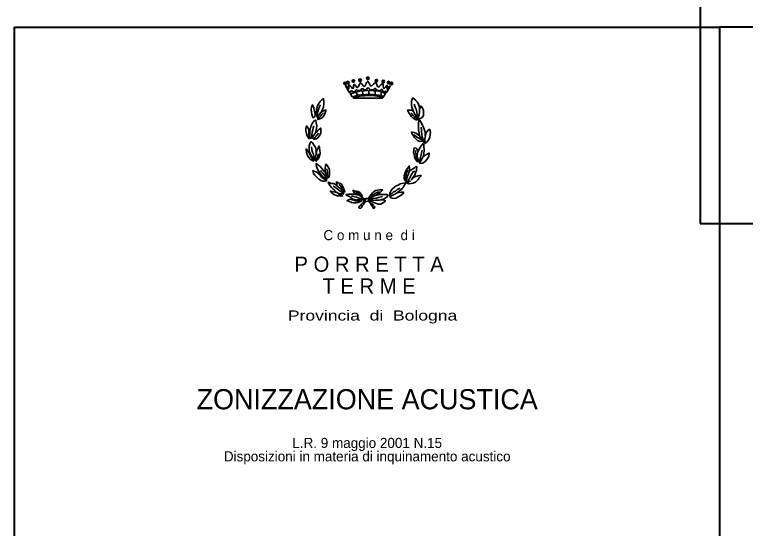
# Model space of a CAD drawing. Extents: x 645880 to 658994, y 884400 to 894744.
# Drawn here: x 645880 to 648057, y 888096 to 889625 of the extents above; entities that cross this region are included whole.
import ezdxf
from ezdxf.enums import TextEntityAlignment as Align

# ---------------------------------------------------------------- set-up
doc = ezdxf.new("R2010")
doc.units = 0
doc.header["$LTSCALE"] = 10
doc.layers.add('62', color=7, linetype='Continuous', lineweight=35)
doc.layers.add('63', color=7, linetype='Continuous', lineweight=35)

msp = doc.modelspace()

# ---------------------------------------------------------------- hatches: boundary and pattern name
at = {"layer": '63'}
for points in [[(646872.77, 889426.73, 1), (646872.77, 889419.06, 1)], [(646889.6, 889431.46, 1), (646889.6, 889423.79, 1)], [(646909.49, 889433.98, 1), (646909.49, 889426.31, 1)], [(646932.74, 889439.66, 1), (646932.74, 889431.99, 1)], [(646958.14, 889432.4, 1), (646958.14, 889424.74, 1)], [(646978.64, 889430.2, 1), (646978.64, 889422.53, 1)], [(646994.86, 889426.73, 1), (646994.86, 889419.06, 1)], [(646864.51, 889424.52, 1), (646864.51, 889416.85, 1)], [(647002.82, 889423.89, 1), (647002.82, 889416.22, 1)]]:
    msp.add_hatch(color=256, dxfattribs=at).paths.add_polyline_path(points)

# ---------------------------------------------------------------- linework, layer by layer
at = {"layer": '62', "lineweight": 40}
msp.add_lwpolyline([(647922.35, 889003.81), (650022.35, 889003.81), (650022.35, 891773.81), (647922.35, 891773.81)], close=True, dxfattribs=at)
at = {"layer": '63'}
for p, q in [((646902.75, 889385.05), (646897.25, 889394.83)), ((646917.44, 889386.94), (646916.22, 889398.29)), ((646935.48, 889388.2), (646935.48, 889398.92)), ((646954.47, 889387.25), (646954.79, 889398.92)), ((646970.99, 889384.1), (646973.75, 889394.2)), ((646758.12, 889261.88), (646757.52, 889255.27)), ((646806.45, 889154.17), (646810.44, 889144.39)), ((646841.61, 889114.78), (646844.37, 889112.57)), ((646853.85, 889104.04), (646855.55, 889101.67)), ((646916.21, 889085.47), (646911.62, 889084.51))]:
    msp.add_line(p, q, dxfattribs=at)
at = {"layer": '63', "lineweight": 40}
for points in [[(645880.32, 889588.16), (647980.32, 889588.16), (647980.32, 884399.72), (645880.32, 884399.72)], [(647980.32, 884399.72), (650080.32, 884399.72), (650080.32, 889588.16), (647980.32, 889588.16)]]:
    msp.add_lwpolyline(points, close=True, dxfattribs=at)
at = {"layer": '63', "lineweight": 13}
msp.add_lwpolyline([(647980.32, 889588.16), (647980.32, 886618.16), (645880.32, 886618.16), (645880.32, 889588.16)], close=True, dxfattribs=at)
at = {"layer": '63'}
for points in [[(646879.19, 889391.36), (646875.83, 889396.7), (646865.73, 889412.8), (646868.16, 889413.13), (646870.92, 889411.22), (646875.83, 889403.96), (646876.14, 889406.81), (646875.53, 889411.87), (646875.21, 889416.91), (646879.5, 889413.13), (646883.46, 889409.33), (646886.24, 889405.54), (646889.28, 889406.18), (646889.6, 889408.7), (646889.9, 889412.8), (646890.51, 889418.17), (646894.8, 889415), (646896.63, 889412.17), (646898.46, 889410.28), (646899.69, 889408.7), (646902.14, 889408.7), (646903.98, 889410.59), (646908.56, 889419.43), (646911, 889423.52), (646914.38, 889419.43), (646918.35, 889413.44), (646920.8, 889411.22), (646923.56, 889411.87), (646925.4, 889415.65), (646928.46, 889422.91), (646932.12, 889427.32), (646935.48, 889422.58), (646938.56, 889416.91), (646941, 889413.13), (646942.53, 889413.13), (646944.99, 889414.37), (646949.58, 889418.17), (646955.07, 889423.21), (646957.52, 889421.96), (646959.96, 889414.7)], [(646954.16, 889404.92), (646952.01, 889404.92), (646951.1, 889404.29), (646950.48, 889402.7), (646950.48, 889401.76), (646950.48, 889401.13), (646937.64, 889402.09), (646937.64, 889403.96), (646935.8, 889405.87), (646933.67, 889407.13), (646931.52, 889406.5), (646929.99, 889405.87), (646929.68, 889404.61), (646929.68, 889401.76), (646929.68, 889400.83), (646919.88, 889400.83), (646919.88, 889403.33), (646918.05, 889404.29), (646916.22, 889404.61), (646914.38, 889404.29), (646912.85, 889403.33), (646912.23, 889402.4), (646912.23, 889401.13), (646912.23, 889400.18), (646912.23, 889399.88), (646902.14, 889398.92), (646900.92, 889400.18), (646899.69, 889400.83), (646897.86, 889400.83), (646897.25, 889400.5), (646896.03, 889399.55), (646895.4, 889398.92), (646895.4, 889397.98), (646895.4, 889397.03), (646888.68, 889394.5), (646888.07, 889396.7), (646886.24, 889398.29), (646882.56, 889398.62), (646881.35, 889397.35), (646880.72, 889395.77)], [(646959.96, 889414.7), (646961.51, 889410.92), (646963.65, 889409.33), (646966.08, 889410.28), (646967.63, 889412.48), (646971.6, 889415.96), (646976.19, 889419.74), (646978.64, 889418.17), (646978.64, 889413.13), (646979.55, 889407.74), (646980.18, 889405.87), (646981.08, 889405.87), (646982.31, 889406.18), (646985.07, 889409.33), (646990.26, 889415), (646990.88, 889411.22), (646990.26, 889405.87), (646990.56, 889402.4), (646992.11, 889400.83), (646993.95, 889403.66), (646994.55, 889407.44), (646995.17, 889410.59), (646997.31, 889411.87), (646999.14, 889411.87), (646993.95, 889402.09), (646986.9, 889391.99), (646987.82, 889394.5), (646985.37, 889397.35), (646983.54, 889396.4), (646983.24, 889395.14), (646976.19, 889397.03), (646976.19, 889400.5), (646975.28, 889402.7), (646972.83, 889402.7), (646971.3, 889401.44), (646970.07, 889399.88), (646970.07, 889398.62), (646957.52, 889401.44), (646956.3, 889404.29), (646954.16, 889404.92)], [(646880.72, 889395.77), (646881.35, 889393.57), (646881.03, 889392.62), (646879.19, 889391.36)], [(646782, 889320.85), (646782, 889328.11), (646783.22, 889335.68), (646785.36, 889342.3), (646787.51, 889348.28), (646791.18, 889356.17)], [(647082.39, 889317.88), (647079.33, 889326.23), (647078.1, 889336.01), (647076.27, 889343.59), (647073.83, 889349.57), (647071.08, 889358.72)], [(647086.68, 889343.9), (647086.07, 889334.75), (647085.15, 889327.49), (647083.62, 889321.82), (647081.16, 889313.93)], [(646779.24, 889326.85), (646782, 889320.85), (646779.24, 889326.85)], [(646793.63, 889335.04), (646787.21, 889327.78), (646782.3, 889320.85)], [(646783.52, 889312.64), (646788.12, 889319.9), (646791.48, 889322.72), (646795.46, 889328.11), (646800.96, 889332.52)], [(647068.62, 889337.27), (647072.6, 889329.07), (647076.9, 889322.77), (647079.02, 889318.03), (647081.16, 889313.93), (647075.04, 889317.08), (647071.38, 889320.86), (647067.71, 889324.97), (647063.42, 889329.7), (647060.97, 889332.55)], [(646757.52, 889255.27), (646763.64, 889261.88), (646766.09, 889267.24), (646766.7, 889275.44), (646768.83, 889282.39), (646769.75, 889288.06), (646771.28, 889293.74)], [(646771.28, 889254.62), (646775.57, 889259.99), (646778.94, 889263.77), (646783.52, 889268.83), (646785.96, 889272.61)], [(647104.38, 889241.12), (647098.58, 889250.57), (647094.9, 889260.98), (647093.37, 889269.82), (647092.46, 889278.32), (647091.24, 889289.69)], [(646775.27, 889271.35), (646770.98, 889265.03), (646767.62, 889259.05)], [(647091.84, 889253.42), (647086.34, 889256.87), (647079, 889260.35), (647070.42, 889267.61)], [(647096.75, 889248.04), (647091.84, 889253.42), (647090.31, 889258.15), (647086.95, 889264.46)], [(647102.87, 889260.35), (647102.25, 889254.98), (647101.64, 889252.16), (647104.38, 889241.12)], [(646773.12, 889193.36), (646772.21, 889199.51), (646770.36, 889209.61), (646767, 889217.8), (646766.09, 889224.43), (646764.84, 889231.39)], [(646778.33, 889209.31), (646776.48, 889200.77), (646775.27, 889195.1)], [(646778.93, 889188.8), (646781.07, 889195.42), (646783.82, 889203.62), (646784.13, 889211.18)], [(647078.87, 889189.43), (647077.8, 889196.99), (647076.26, 889208.03), (647075.03, 889215.29), (647075.03, 889220.66)], [(647081.16, 889217.81), (647080.55, 889211.51), (647079.92, 889205.83), (647079.92, 889201.4), (647081.16, 889195.1)], [(647097.06, 889202.36), (647093.7, 889194.79), (647086.98, 889185.32), (647087.28, 889192.9), (647089.11, 889199.53), (647091.24, 889207.4), (647092.79, 889213.72), (647094.6, 889221.28)], [(646815.63, 889139.66), (646812.56, 889147.54), (646811.96, 889156.06), (646810.44, 889165.82)], [(646807.98, 889133.03), (646806.75, 889142.81), (646802.76, 889148.48), (646798.8, 889153.22), (646794.51, 889157.63), (646791.77, 889161.41)], [(647047.23, 889127.05), (647043.56, 889136.51), (647045.7, 889143.44), (647047.85, 889155.11), (647050.59, 889159.52), (647052.12, 889162.07)], [(647056.4, 889158.91), (647054.27, 889155.11), (647052.42, 889148.48), (647051.21, 889145.66), (647049.06, 889138.4), (647047.23, 889132.73), (647047.23, 889127.05)], [(647048.76, 889123.9), (647053.04, 889131.16), (647057.33, 889139.66), (647062.83, 889149.44), (647067.72, 889157.32), (647072.33, 889159.52)], [(647048.76, 889123.9), (647055.18, 889127.68), (647060.07, 889130.83)], [(646860.59, 889091.12), (646855.08, 889096.16), (646850.18, 889099.94), (646845.59, 889103.11), (646841.31, 889106.57), (646836.72, 889110.04), (646832.75, 889112.24), (646829.07, 889115.08)], [(646844.37, 889112.57), (646849.26, 889108.46), (646853.85, 889104.04)], [(646864.26, 889096.79), (646858.44, 889104.37), (646854.47, 889109.42), (646851.11, 889115.08), (646848.03, 889118.24), (646845.9, 889119.2)], [(646916.21, 889085.47), (646912.55, 889090.51), (646908.26, 889095.55), (646903.37, 889098.38), (646896.62, 889099.96), (646890.2, 889101.55), (646888.37, 889102.16), (646889.88, 889098.71), (646892.96, 889093.66), (646896.62, 889092.71), (646900.61, 889092.38), (646905.66, 889087.67)], [(646996.82, 889088.59), (647004.17, 889092.68), (647009.36, 889097.72), (647015.18, 889099.63), (647020.08, 889104.67), (647028.65, 889108.46)], [(646919.88, 889078.51), (646912.23, 889077.88), (646907.64, 889078.21), (646903.37, 889080.08), (646898.76, 889081.67), (646893.57, 889082.62), (646888.68, 889084.51), (646883.46, 889084.82)], [(646905.2, 889074.08), (646897.55, 889074.08), (646891.43, 889075.04), (646886.52, 889077.26)], [(646913.93, 889084.99), (646907.94, 889091.12), (646902.75, 889094.6), (646896.62, 889097.75)], [(646905.66, 889087.67), (646909.19, 889086.4), (646911.62, 889084.51), (646916.21, 889085.47)], [(646927.53, 889077.88), (646925.7, 889075.04), (646924.16, 889072.52), (646923.56, 889068.1)], [(646933.35, 889075.67), (646942.83, 889083.88), (646948.04, 889088.6), (646954.16, 889093.03), (646961.19, 889096.81), (646967.63, 889097.75)], [(646933.95, 889069.37), (646943.15, 889076), (646949.88, 889077.88), (646958.75, 889079.14), (646964.57, 889080.71), (646972.2, 889082.62), (646975.88, 889083.26)], [(646955.07, 889086.4), (646949.57, 889084.51), (646945.28, 889081.34), (646940.69, 889078.21), (646938.56, 889075.04), (646934.27, 889071.88)], [(647020.38, 889094.89), (647018.24, 889093.31), (647012.72, 889091.11), (647009.06, 889088.9), (647005.08, 889087), (647002.62, 889085.42), (647000.79, 889084.16), (646998.66, 889082.27)], [(646881.02, 889075.36), (646885.92, 889073.47), (646890.51, 889072.52), (646895.4, 889071.26), (646901.82, 889070.63), (646908.56, 889070.63), (646914.36, 889070.3)], [(646933.95, 889069.37), (646944.36, 889071.88), (646955.07, 889073.15), (646965.78, 889072.52), (646971.3, 889073.78)]]:
    msp.add_lwpolyline(points, dxfattribs=at)
for points in [[(646881.03, 889389.14), (646886.24, 889380.62), (646893.57, 889382.84), (646902.75, 889385.05), (646912.85, 889385.99), (646926.62, 889387.25), (646938.86, 889388.2), (646948.97, 889387.25), (646965.78, 889385.66), (646974.96, 889383.16), (646978.64, 889379.36), (646985.37, 889390.09), (646976.81, 889393.25), (646968.24, 889396.09), (646959.06, 889397.98), (646949.27, 889398.62), (646937.03, 889398.92), (646922.64, 889398.62), (646908.87, 889397.03), (646897.25, 889394.83), (646888.07, 889391.66)], [(646896.32, 889379.36), (646910.1, 889382.21), (646922.64, 889383.46), (646935.48, 889384.42), (646945.59, 889384.1), (646960.28, 889382.53), (646970.99, 889380.95), (646976.64, 889376.68), (646889.13, 889376.06)], [(646782, 889320.85), (646779.24, 889326.85), (646778.63, 889333.76), (646779.84, 889342.6), (646782.6, 889352.39), (646785.36, 889359.97), (646790.25, 889366.58), (646795.46, 889371.64), (646800.36, 889375.42), (646801.89, 889367.84), (646801.89, 889358.69), (646800.05, 889350.5), (646797.3, 889342.6), (646793.63, 889335.04), (646798.52, 889337.89), (646807.7, 889341.35), (646807.38, 889338.5), (646804.94, 889330.31), (646801.89, 889324.31), (646796.39, 889318.31), (646789.64, 889314.86), (646783.52, 889312.64), (646782.3, 889320.85)], [(647081.16, 889313.93), (647090.34, 889316.78), (647094.32, 889318.66), (647098.01, 889324.64), (647098.31, 889330.97), (647098.31, 889340.42), (647096.78, 889344.22), (647094.63, 889350.2), (647090.34, 889353.68), (647089.43, 889349.9), (647086.68, 889343.9), (647086.07, 889350.2), (647083.62, 889358.72), (647079.33, 889365.67), (647075.04, 889370.39), (647066.79, 889377.34), (647065.26, 889375.13), (647062.8, 889367.87), (647062.5, 889363.15), (647062.8, 889356.52), (647064.03, 889350.2), (647065.56, 889344.85), (647068.62, 889337.27), (647062.2, 889340.42), (647055.78, 889340.74), (647050.88, 889341.07), (647054.85, 889332.86), (647058.84, 889326.56), (647062.8, 889321.82), (647067.71, 889317.08), (647073.21, 889312.67), (647078.72, 889311.1)], [(646769.75, 889317.68), (646767.62, 889322.42), (646765.47, 889328.72), (646764.54, 889334.41), (646763.94, 889341.67), (646764.54, 889349.23), (646766.7, 889355.54), (646767.62, 889356.8), (646770.06, 889352.39), (646771.59, 889347.98), (646773.12, 889340.72), (646774.95, 889333.15), (646775.57, 889327.46), (646774.64, 889321.79)], [(646757.52, 889255.27), (646752.32, 889264.1), (646750.16, 889271.66), (646748.34, 889278.92), (646748.34, 889286.48), (646750.16, 889293.74), (646755.98, 889285.54), (646756.59, 889280.48), (646756.91, 889271.66), (646758.12, 889261.88), (646759.35, 889270.72), (646759.35, 889277.02), (646760.88, 889286.48), (646762.41, 889290.26), (646764.24, 889295.32), (646766.7, 889301), (646769.45, 889304.78), (646774.04, 889309.82), (646777.41, 889311.4), (646778.94, 889303.52), (646780.16, 889294.04), (646779.24, 889285.85), (646777.71, 889277.66), (646775.27, 889271.35), (646779.54, 889275.76), (646784.13, 889280.8), (646789.95, 889284.91), (646792.1, 889287.43), (646792.1, 889280.18), (646792.1, 889273.24), (646790.87, 889268.18), (646787.81, 889263.77), (646783.83, 889258.72), (646779.84, 889255.58), (646775.27, 889254.62), (646771.28, 889254.62), (646767.62, 889259.05)], [(647104.38, 889241.12), (647108.99, 889246.16), (647113.56, 889252.16), (647116.94, 889259.72), (647118.47, 889267.91), (647118.78, 889273.91), (647117.85, 889279.58), (647116.02, 889284.01), (647113.56, 889281.8), (647110.2, 889278.65), (647105.31, 889272.65), (647104.08, 889264.76), (647103.48, 889262.57), (647102.87, 889276.12), (647098.88, 889289.36), (647094.3, 889297.88), (647089.4, 889306.72), (647085.72, 889313.98), (647083.58, 889302.94), (647083.58, 889288.75), (647083.89, 889282.43), (647085.42, 889273.6), (647086.95, 889264.46), (647077.77, 889271.71), (647070.72, 889274.24), (647062.16, 889275.5), (647064, 889271.39), (647068.29, 889264.76), (647071.34, 889259.08), (647075.31, 889254.98), (647080.2, 889250.24), (647087.27, 889247.74), (647096.75, 889248.04)], [(646770.98, 889191.64), (646770.06, 889196.36), (646764.84, 889204.55), (646759.95, 889214.02), (646758.12, 889220.96), (646758.12, 889229.18), (646758.12, 889234.84), (646760.58, 889243.67), (646764.24, 889247.47), (646767.92, 889243.04), (646772.51, 889235.8), (646777.1, 889229.48), (646778.93, 889221.28), (646778.33, 889209.31), (646779.84, 889217.5), (646782.6, 889223.48), (646787.19, 889234.52), (646789.02, 889229.18), (646789.95, 889219.7), (646790.25, 889212.14), (646787.19, 889201.4), (646784.75, 889195.1), (646778.93, 889188.8), (646775.27, 889195.1)], [(647086.67, 889181.54), (647095.23, 889183.12), (647102.28, 889186.9), (647108.7, 889193.53), (647114.19, 889202.36), (647115.42, 889212.77), (647113.28, 889212.14), (647107.17, 889208.66), (647097.06, 889202.36), (647099.51, 889211.18), (647100.74, 889222.55), (647099.51, 889232.65), (647098.91, 889239.26), (647096.15, 889240.84), (647091.24, 889234.85), (647085.74, 889224.44), (647081.16, 889217.81), (647079.63, 889223.18), (647076.26, 889227.28), (647070.75, 889228.22), (647069.52, 889223.18), (647068.92, 889214.03), (647070.44, 889209.62), (647071.37, 889202.05), (647073.51, 889196.06), (647076.87, 889192.27), (647080.85, 889186.58), (647081.16, 889188.16), (647081.16, 889195.1), (647086.98, 889185.32)], [(646772.51, 889188.47), (646766.7, 889191.31), (646761.18, 889194.47), (646757.82, 889198.57), (646753.53, 889203.92), (646751.7, 889208.96), (646749.54, 889214.96), (646748.64, 889225.39), (646756.59, 889215.92), (646759.65, 889208.35), (646763.33, 889201.4), (646767.6, 889195.42), (646770.98, 889191.64)], [(646807.98, 889133.03), (646804.62, 889137.44), (646797.59, 889142.81), (646793.28, 889148.17), (646788.71, 889154.78), (646785.03, 889161.41), (646781.66, 889168.04), (646779.21, 889174.36), (646778.91, 889179.08), (646778.91, 889182.25), (646784.42, 889177.82), (646791.15, 889172.15), (646796.96, 889166.47), (646801.25, 889158.91), (646806.45, 889154.17), (646805.54, 889161.74), (646805.84, 889167.1), (646806.45, 889175.62), (646807.98, 889180.34), (646811.34, 889175.62), (646815.02, 889170.56), (646817.16, 889166.15), (646818.08, 889159.84), (646818.38, 889153.52), (646818.38, 889148.48), (646817.76, 889144.07), (646815.63, 889139.66), (646810.44, 889144.39), (646810.44, 889136.18)], [(647048.76, 889123.9), (647055.18, 889121.69), (647061.6, 889121.99), (647068.04, 889123.58), (647074.16, 889126.1), (647078.43, 889130.83), (647082.12, 889134.31), (647085.48, 889139.36), (647089.76, 889143.44), (647091.3, 889146.28), (647087.63, 889146.28), (647082.72, 889145.35), (647075.37, 889143.44), (647070.78, 889141.24), (647062.47, 889133.78), (647064.96, 889136.83), (647068.95, 889142.2), (647073.54, 889149.13), (647073.84, 889152.91), (647077.22, 889160.48), (647077.83, 889166.78), (647078.15, 889172.48), (647075.99, 889172.78), (647072.01, 889169.32), (647068.64, 889167.43), (647061.92, 889163.32), (647056.4, 889158.91), (647056.4, 889163.95), (647056.4, 889169.63), (647056.1, 889174.69), (647053.67, 889171.21), (647049.68, 889166.15), (647045.7, 889159.87), (647042.34, 889152.28), (647040.48, 889146.62), (647040.48, 889137.79), (647041.71, 889132.4), (647047.23, 889127.05)], [(646807.98, 889133.03), (646801.56, 889136.18), (646795.74, 889140.61), (646791.15, 889145.66), (646786.56, 889150.07), (646782.27, 889154.78), (646774.92, 889158.26), (646768.5, 889160.17), (646770.66, 889151.96), (646774.32, 889146.91), (646781.06, 889140.92), (646786.56, 889135.24), (646792.38, 889131.44), (646798.5, 889129.24), (646804.92, 889128.92), (646809.83, 889130.83)], [(646860.59, 889091.12), (646854.77, 889091.42), (646848.35, 889092.07), (646840.38, 889095.2), (646833.06, 889102.46), (646828.44, 889106.24), (646824.48, 889110.67), (646820.19, 889115.72), (646816.52, 889121.08), (646814.69, 889126.76), (646817.45, 889125.19), (646822.95, 889122.67), (646831.52, 889122.02), (646838.87, 889116.98), (646841.61, 889114.78), (646840.38, 889120.13), (646839.17, 889125.19), (646838.87, 889127.08), (646844.67, 889124.87), (646851.11, 889122.34), (646854.77, 889119.2), (646857.23, 889115.41), (646859.36, 889110.98), (646861.2, 889105.94), (646863.03, 889101.53), (646864.26, 889096.79), (646860.59, 889099.63), (646855.55, 889101.67), (646857.23, 889099.33), (646859.36, 889093.96)], [(646996.82, 889088.59), (646998.96, 889095.83), (647002.32, 889101.5), (647006.3, 889106.87), (647011.8, 889111.28), (647017.32, 889115.08), (647022.83, 889117.91), (647028.65, 889121.38), (647034.47, 889122.65), (647043.33, 889124.23), (647044.56, 889123.91), (647041.49, 889117.91), (647040.27, 889114.46), (647037.51, 889110.34), (647034.77, 889107.5), (647031.39, 889103.42), (647028.03, 889101.2), (647020.24, 889094.87), (647025.89, 889095.52), (647031.69, 889096.16), (647038.74, 889096.46), (647039.36, 889094.24), (647031.69, 889087.63), (647023.14, 889082.27), (647017.01, 889079.12), (647009.06, 889078.16), (647000.79, 889079.42), (646998.66, 889082.27)], [(646830.6, 889098.05), (646840.38, 889095.2), (646846.2, 889090.16), (646857.54, 889085.44), (646851.11, 889085.12), (646842.54, 889085.75), (646836.42, 889087.34), (646831.52, 889090.16), (646825.7, 889094.9), (646820.49, 889100.26), (646821.72, 889099.94)], [(646933.35, 889075.67), (646937.33, 889083.26), (646942.22, 889089.88), (646946.82, 889094.3), (646951.4, 889098.38), (646955.69, 889101.22), (646961.19, 889102.16), (646967.31, 889103.42), (646972.83, 889103.75), (646977.11, 889103.42), (646975.88, 889102.16), (646973.12, 889099.34), (646969.76, 889095.55), (646963.64, 889092.08), (646955.07, 889086.4), (646960.58, 889087.97), (646968.23, 889089.25), (646975.88, 889090.18), (646982.91, 889090.18), (646990.56, 889089.55), (646992.11, 889086.4), (646990.56, 889082.62), (646985.67, 889079.47), (646980.78, 889076.93), (646971.3, 889073.78), (646981.38, 889073.15), (646985.06, 889070), (646978.94, 889065.89), (646970.99, 889061.18), (646964.25, 889061.18), (646958.15, 889062.43), (646952.33, 889064.63), (646947.42, 889066.84), (646944.06, 889069.37), (646933.95, 889069.37), (646934.27, 889071.88)], [(646914.36, 889070.3), (646908.87, 889067.8), (646903.05, 889066.22), (646898.16, 889065.26), (646893.87, 889064.96), (646889.6, 889065.26), (646884.08, 889066.22), (646879.5, 889067.8), (646874.6, 889069.67), (646870.31, 889071.58), (646872.75, 889072.22), (646877.04, 889074.43), (646881.02, 889075.36), (646886.52, 889077.26), (646882.55, 889080.08), (646877.96, 889083.56), (646874.6, 889085.12), (646870.31, 889086.71), (646867.56, 889089.25), (646870.02, 889089.55), (646875.83, 889090.82), (646882.25, 889091.12), (646888.98, 889090.51), (646895.7, 889089.88), (646902.12, 889088.92), (646909.19, 889086.4), (646914.08, 889082.62), (646919.88, 889078.51), (646916.52, 889075.04), (646909.47, 889074.43), (646905.2, 889074.08)], [(646923.56, 889068.1), (646919.58, 889069.67), (646919.27, 889072.84), (646922.94, 889077.26), (646927.53, 889077.88), (646930.29, 889078.51), (646933.35, 889075.67), (646934.27, 889071.88), (646933.95, 889069.37), (646927.85, 889068.74)], [(646923.56, 889068.1), (646918.67, 889065.89), (646913.46, 889061.18), (646910.4, 889057.06), (646906.73, 889054.22), (646905.81, 889050.14), (646910.4, 889048.22), (646913.46, 889051.07), (646916.21, 889056.76), (646920.18, 889060.54)], [(646933.95, 889069.37), (646945.58, 889061.8), (646948.64, 889057.7), (646953.54, 889052.65), (646951.71, 889049.18), (646949.27, 889048.22), (646946.51, 889053.59), (646942.83, 889058.96), (646939.47, 889063.39), (646936.1, 889066.52)]]:
    msp.add_lwpolyline(points, close=True, dxfattribs=at)
for centre in [(646872.77, 889422.89), (646889.6, 889427.62), (646909.49, 889430.15), (646932.74, 889435.83), (646958.14, 889428.57), (646978.64, 889426.36), (646994.86, 889422.89), (646864.51, 889420.68), (647002.82, 889420.05)]:
    msp.add_circle(centre, 3.83, dxfattribs=at)

# ---------------------------------------------------------------- texts
for s, height, p in [('C o m u n e  d i', 30, (646936.33, 888953.72)), ('P O R R E T T A', 45, (646936.33, 888859.82)), ('T E R M E', 45, (646936.33, 888794.82)), ('ZONIZZAZIONE ACUSTICA', 60, (646930.69, 888450.08)), ('L.R. 9 maggio 2001 N.15', 30, (646930.68, 888335.03)), ('Disposizioni in materia di inquinamento acustico', 30, (646930.68, 888295.03))]:
    msp.add_text(s, height=height, dxfattribs=at).set_placement(p, align=Align.CENTER)
at = {"layer": '63', "width": 1.3}
msp.add_text('Provincia  di  Bologna', height=30, dxfattribs=at).set_placement((646946.68, 888714.48), align=Align.CENTER)

doc.saveas('drawing.dxf')
